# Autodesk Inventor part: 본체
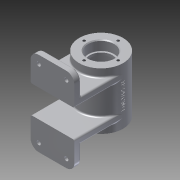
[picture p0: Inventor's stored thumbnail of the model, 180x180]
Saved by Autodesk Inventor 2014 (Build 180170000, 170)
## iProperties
Created: 2017-02
Part Number: 본체
Material: 알루미늄 6061
Document SubType Name: Modeling
Designer: 601-
Mass: 356.065 g
Surface Area: 422.773 cm^2
Volume: 131.389 cm^3
Density: 2.71 g/cm^3
Appearance: 알루미늄 - 평지
Author: 601-
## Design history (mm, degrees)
sketch "스케치4"
  geometry: L1 (0, 0)-(0, 60); C1 r 27 at (0, 60)
  constraints: 2 end point, 1 centre point, 1 coincident, 1 vertical
  dimensions: "d4" = 60 distance of L1.start L1.end; "d5" = 54 diameter of C1
extrude "돌출2" new body sketch "스케치4" stored distance "d6" = 70; taper "d7" = 0 deg
sketch "스케치5"
  geometry: L1 (-27, -52)-(27, -52); L2 (27, -52)-(27, 52); L3 (27, 52)-(-27, 52); L4 (-27, 52)-(-27, -52); L5 (-27, -52)-(27, 52); L6 (27, -52)-(-27, 52); L7 (0, 0)-(0, -17); L8 (0, -17)-(27, -17); L9 (0, -17)-(-27, -17); L10 (0, 0)-(0, 17); L11 (0, 17)-(27, 17); L12 (0, 17)-(-27, 17)
  constraints: 24 end point, 6 perpendicular, 4 point on line, 3 parallel, 2 midpoint, 1 horizontal
  dimensions: "d8" = 54 distance of L3.end L2.end; "d9" = 104 distance of L2.end L1.end; "d10" = 17 distance of L7.start L7.end; "d11" = 17 distance of L7.start L10.end
extrude "돌출3" join sketch "스케치5" distance "d12" = 8; taper "d13" = 0 deg
sketch "스케치7"
  geometry: L1 (27, -52)-(27, -17) reference; L2 (-27, -17)-(27, -17); L3 (27, -17)-(27, -25); L4 (27, -25)-(-27, -25); L5 (-27, -25)-(-27, -17); L6 (-27, 17)-(27, 17); L7 (27, 17)-(27, 25); L8 (27, 25)-(-27, 25); L9 (-27, 25)-(-27, 17); 1 further point
  constraints: 16 end point, 4 parallel, 2 horizontal, 2 perpendicular, 1 point on line
  dimensions: "d22" = 8 distance of L2.end L3.end; "d23" = 8 distance of L7.end L6.end; "d24" = 54 distance between parallel lines of L9 L7
extrude "돌출4" join sketch "스케치7" stored distance "d25" = 54; taper "d26" = 0 deg
sketch "스케치8"
  geometry: L1 (87, 35)-(33, 35) reference; L2 (60, 35)-(60, -35); L3 (33, -35)-(87, -35) reference; L4 (60, 35)-(76, 35); L5 (76, 35)-(76, 23); L6 (76, 23)-(74, 23); L7 (74, 23)-(74, 20); L8 (60, -35)-(76, -35); L9 (76, -35)-(76, -23); L10 (76, -23)-(74, -23); L11 (74, -23)-(74, -20); L12 (74, -20)-(82, -20); L13 (82, -20)-(82, 20); L14 (82, 20)-(74, 20); 1 further point
  constraints: 24 end point, 6 perpendicular, 2 midpoint, 2 parallel, 2 point on line
  dimensions: "d27" = 16 distance of L2.start L4.end; "d28" = 12 distance of L4.end L5.end; "d29" = 2 distance of L5.end L6.end; "d30" = 3 distance of L6.end L7.end; "d31" = 16 distance of L2.end L8.end; "d32" = 12 distance of L8.end L9.end; "d33" = 2 distance of L9.end L10.end; "d34" = 3 distance of L10.end L11.end; "d35" = 8 distance of L11.end L12.end; "d36" = 40 distance of L12.end L13.end
revolve "회전1" sketch "스케치8" stored, may be unused: angle "d37" = 90 deg
sketch "스케치9"
  geometry: L1 (44, 35)-(76, 35) reference; L2 (60, 35)-(60, 10); L3 (60, 10)-(87, 10); L4 (87, 10)-(92, 10); L5 (92, 10)-(92, 15); L6 (92, 15)-(82.5, 15); L7 (82.5, 15)-(82.5, 10); L8 (92, 10)-(82.5, 10); 1 further point
  constraints: 14 end point, 4 perpendicular, 1 collinear, 1 midpoint, 1 point on line
  dimensions: "d39" = 25 distance of L2.start L2.end; "d40" = 27 distance of L2.end L3.end; "d41" = 5 distance of L3.end L4.end; "d42" = 5 distance of L4.end L5.end; "d43" = 9.5 distance of L5.end L6.end; "d44" = 5 distance of L6.end L7.end
revolve "회전2" sketch "스케치9" stored, may be unused: angle "d45" = 90 deg
sketch "스케치10"
  geometry: L1 (0, 60)-(-16.339, 34.84); L2 (0, 60)-(30, 60); L3 (-16.339, 34.84)-(-11.307, 31.572); L4 (-11.307, 31.572)-(-8.312, 36.185); L5 (-8.312, 36.185)-(-13.344, 39.453); L6 (-13.344, 39.453)-(-16.339, 34.84); C1 r 14 at (0, 60) reference; 1 further point
  constraints: 12 end point, 2 perpendicular, 1 collinear, 1 equal length, 1 horizontal, 1 parallel, 1 point on line
  dimensions: "d127" = 30 distance of L1.start L1.end; "d128" = 123 deg angle of L1 L2; "d129" = 6 distance of L1.end L3.end; "d130" = 5.5 distance of L3.end L4.end
revolve "회전3" sketch "스케치10" stored, may be unused: angle "d50" = 90 deg
sketch "스케치12" dims "d53" = 9, "d55" = 9, "d56" = 9, "d57" = 9
  geometry: L1 (17, 42)-(-17, 42); L2 (-17, 42)-(-17, -42); L3 (-17, -42)-(17, -42); L4 (17, -42)-(17, 42); L5 (17, 42)-(-17, -42); L6 (-17, 42)-(17, -42); L7 (-12.5, 39.402)-(-17, 36.804); L8 (-17, 36.804)-(-21.5, 39.402); L9 (-21.5, 39.402)-(-21.5, 44.598); L10 (-21.5, 44.598)-(-17, 47.196); L11 (-17, 47.196)-(-12.5, 44.598); L12 (-12.5, 44.598)-(-12.5, 39.402); L13 (12.5, 44.598)-(17, 47.196); L14 (17, 47.196)-(21.5, 44.598); L15 (21.5, 44.598)-(21.5, 39.402); L16 (21.5, 39.402)-(17, 36.804); L17 (17, 36.804)-(12.5, 39.402); L18 (12.5, 39.402)-(12.5, 44.598); L19 (12.5, -39.402)-(17, -36.804); L20 (17, -36.804)-(21.5, -39.402); L21 (21.5, -39.402)-(21.5, -44.598); L22 (21.5, -44.598)-(17, -47.196); L23 (17, -47.196)-(12.5, -44.598); L24 (12.5, -44.598)-(12.5, -39.402); L25 (-12.5, -44.598)-(-17, -47.196); L26 (-17, -47.196)-(-21.5, -44.598); L27 (-21.5, -44.598)-(-21.5, -39.402); L28 (-21.5, -39.402)-(-17, -36.804); L29 (-17, -36.804)-(-12.5, -39.402); L30 (-12.5, -39.402)-(-12.5, -44.598); 13 further points
  constraints: 60 end point, 8 coincident, 6 midpoint, 4 horizontal alignment, 4 point on line, 2 parallel, 1 horizontal, 1 perpendicular, 60 other
  dimensions: "d51" = 34 distance of L3.end L2.end; "d52" = 84 distance of L2.end L1.end
extrude "돌출5" cut sketch "스케치12" distance "d58" = 3; taper "d59" = 0 deg
sketch "스케치14"
  geometry: L1 (-17, 42)-(17, 42); L2 (17, 42)-(17, -42); L3 (17, -42)-(-17, -42); L4 (-17, -42)-(-17, 42); L5 (-17, 42)-(17, -42); L6 (17, 42)-(-17, -42); 1 further point
  constraints: 12 end point, 2 midpoint, 2 parallel, 1 horizontal, 1 perpendicular
  dimensions: "d60" = 34 distance of L2.end L3.end; "d61" = 84 distance of L1.end L2.end
hole "구멍1" sketch "스케치14" at (-17, -42), (17, -42), (17, 42), (-17, 42) diameter "d62" = 5; stored, may be unused: countersink angle "d66" = 90 deg, drill point angle "d68" = 118 deg; dims "d63" = 6, "d64" = 4, "d65" = 2, "d67" = 8
hole "구멍2" diameter "d71" = 5.188; stored, may be unused: countersink angle "d75" = 90 deg, drill point angle "d77" = 118 deg; dims "d69" = 10, "d70" = 10, "d72" = 20, "d73" = 4, "d74" = 2, "d76" = 20
hole "구멍3" diameter "d80" = 5.188; stored, may be unused: countersink angle "d84" = 90 deg, drill point angle "d86" = 118 deg; dims "d81" = 20, "d82" = 4, "d83" = 2, "d85" = 20, "d131" = 10, "d132" = 10
node "작업 평면1"
sketch "스케치15"
  geometry: L1 (27, 35)-(-27, 35) reference; L2 (27, -35)-(27, 35) reference; L3 (27, 35)-(27, 0); L4 (27, 0)-(0, 0); 2 further points
  constraints: 4 end point, 1 coincident, 1 midpoint, 1 perpendicular, 1 other
  dimensions: "d87" = 35 distance of L2.end L3.end; "d88" = 27 distance of L3.end L4.end
feature "엠보싱1" sketch "스케치15" dims "d5" = 54, "d89" = 0.5, "d90" = 0
fillet "모깎기1" dims "d91" = 10
fillet "모깎기2" dims "d92" = 0.3
fillet "모깎기3" dims "d93" = 3
sketch "스케치16"
  geometry: L1 (0, 0)-(0, 21); C1 r 27 at (0, 0) reference; 1 further point
  constraints: 2 end point, 1 vertical
  dimensions: "d94" = 21 distance of L1.start L1.end
hole "구멍4" sketch "스케치16" at (0, 21) diameter "d95" = 3.242; stored, may be unused: countersink angle "d99" = 90 deg, drill point angle "d101" = 118 deg; dims "d96" = 8, "d97" = 4, "d98" = 2, "d100" = 10
sketch "스케치17"
  geometry: L1 (0, 0)-(0, 21); C1 r 27 at (0, 0) reference; 1 further point
  constraints: 2 end point, 1 vertical
  dimensions: "d106" = 21 distance of L1.start L1.end
hole "구멍5" sketch "스케치17" at (0, 21) diameter "d107" = 3.242; stored, may be unused: countersink angle "d111" = 90 deg, drill point angle "d113" = 118 deg; dims "d108" = 8, "d109" = 4, "d110" = 2, "d112" = 10
chamfer "모따기1" distance "d117" = 1; stored, may be unused: second distance "d118" = 2, angle "d119" = 45 deg
chamfer "모따기2" distance "d120" = 1; stored, may be unused: second distance "d121" = 2, angle "d122" = 45 deg
fillet "모깎기4" dims "d123" = 2
fillet "모깎기5" dims "d124" = 2
fillet "모깎기6" dims "d125" = 2
fillet "모깎기7" dims "d126" = 2
node "솔리드2"
pattern_circular "원형 패턴1" dims angle "d103" = 360 deg
pattern_circular "원형 패턴2" dims angle "d115" = 360 deg
